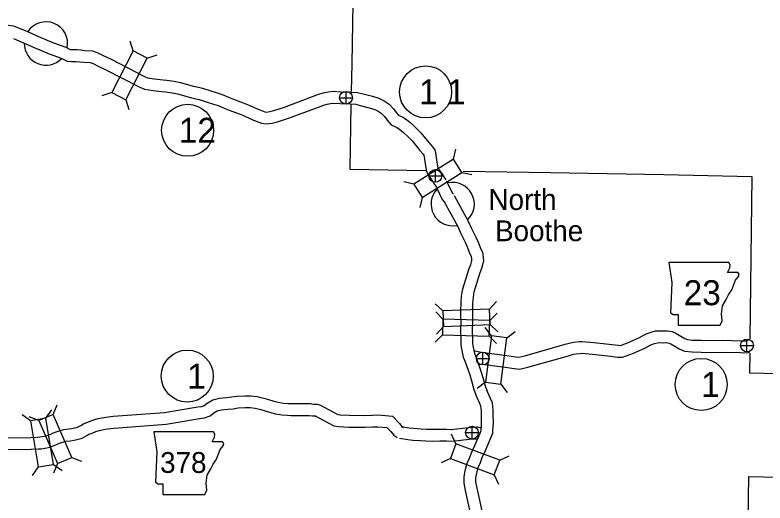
# Model space of a CAD drawing. Extents: x 1382482 to 1385815, y 1168351 to 1170484.
# Drawn here: x 1382910.5 to 1383100.9, y 1170230.6 to 1170354.4 of the extents above; entities that cross this region are included whole.
import ezdxf

# ---------------------------------------------------------------- set-up
doc = ezdxf.new("R2010")
doc.units = 0
for name, color, linetype in [('10', 7, 'Continuous'), ('15', 7, 'Continuous'), ('2', 7, 'Continuous'), ('20', 7, 'Continuous'), ('21', 7, 'Continuous'), ('24', 7, 'Continuous'), ('26', 7, 'Continuous'), ('8', 7, 'Continuous'), ('Default', 7, 'Continuous')]:
    doc.layers.add(name, color=color, linetype=linetype)

msp = doc.modelspace()

# ---------------------------------------------------------------- linework, layer by layer
at = {"layer": '10'}
for points in [[(1383026.89, 1170269.29), (1383028.93, 1170268.84), (1383035.31, 1170268.01), (1383037.57, 1170267.67), (1383038.43, 1170267.6), (1383039.96, 1170267.91), (1383050.2, 1170270.84), (1383051.56, 1170271.21), (1383052.44, 1170271.42), (1383053.74, 1170271.55), (1383054.43, 1170271.58), (1383057.44, 1170271.34), (1383060.56, 1170270.97), (1383062.04, 1170270.78), (1383063.69, 1170270.6), (1383064.19, 1170270.58), (1383066.39, 1170271.41), (1383069.08, 1170272.57), (1383070.72, 1170273.48), (1383071.99, 1170273.89), (1383073.1, 1170274.23), (1383074.17, 1170274.28), (1383075.25, 1170274.24), (1383076.14, 1170274.27), (1383077.31, 1170274.06), (1383078.29, 1170273.66), (1383079.57, 1170272.92), (1383080.52, 1170272.33), (1383081.23, 1170272.04), (1383082.54, 1170271.91), (1383084.76, 1170271.88), (1383090.15, 1170271.77)], [(1383028.1, 1170265.95), (1383028.41, 1170265.88), (1383034.9, 1170265.03), (1383037.21, 1170264.69), (1383038.6, 1170264.57), (1383040.68, 1170265), (1383051.01, 1170267.95), (1383052.3, 1170268.3), (1383052.93, 1170268.45), (1383053.97, 1170268.55), (1383054.39, 1170268.58), (1383057.14, 1170268.35), (1383060.19, 1170268), (1383061.68, 1170267.8), (1383063.48, 1170267.6), (1383064.69, 1170267.56), (1383067.51, 1170268.63), (1383070.4, 1170269.88), (1383071.91, 1170270.71), (1383072.89, 1170271.03), (1383073.62, 1170271.25), (1383074.19, 1170271.28), (1383075.23, 1170271.24), (1383075.92, 1170271.26), (1383076.48, 1170271.16), (1383076.96, 1170270.96), (1383078.03, 1170270.35), (1383079.14, 1170269.66), (1383080.49, 1170269.1), (1383082.38, 1170268.91), (1383084.71, 1170268.88), (1383090.08, 1170268.77)], [(1383096.92, 1170271.94), (1383096.46, 1170271.77), (1383096.01, 1170271.66), (1383095.43, 1170271.6), (1383094.9, 1170271.66), (1383090.15, 1170271.77)], [(1383096.98, 1170268.81), (1383096.54, 1170268.7), (1383095.42, 1170268.58), (1383094.69, 1170268.66), (1383090.08, 1170268.77)], [(1382904.92, 1170247.12), (1382914.45, 1170247.19), (1382916.19, 1170247.3), (1382916.76, 1170247.33), (1382917.97, 1170247.53), (1382918.45, 1170247.64), (1382919.28, 1170247.93), (1382920.67, 1170248.53), (1382921.67, 1170248.87), (1382922.88, 1170249.22), (1382924.13, 1170249.36), (1382924.98, 1170249.48), (1382925.55, 1170249.6), (1382926.03, 1170249.71), (1382926.33, 1170249.81), (1382927.19, 1170250.27), (1382927.84, 1170250.69), (1382928.9, 1170251.12), (1382930, 1170251.54), (1382930.7, 1170251.76), (1382931.58, 1170252), (1382932.48, 1170252.18), (1382933.5, 1170252.34), (1382935.35, 1170252.57), (1382948.45, 1170253.52), (1382952.38, 1170254.17), (1382956.89, 1170254.98), (1382957.93, 1170255.09), (1382958.48, 1170255.3), (1382959.24, 1170255.91), (1382960.7, 1170256.77), (1382962.4, 1170257.16), (1382964.19, 1170257.33), (1382965.48, 1170257.47), (1382966.8, 1170257.67), (1382968.82, 1170257.8), (1382970.32, 1170257.8), (1382971.97, 1170257.59), (1382973.64, 1170257.19), (1382974.82, 1170256.83), (1382976.17, 1170256.44), (1382977.24, 1170256.15), (1382978.6, 1170255.91), (1382979.83, 1170255.83), (1382980.6, 1170255.78), (1382982.29, 1170255.8), (1382983.65, 1170255.81), (1382985.37, 1170255.81), (1382986.26, 1170255.67), (1382987.2, 1170255.64), (1382988.06, 1170255.4), (1382988.93, 1170254.87), (1382992.4, 1170253.02), (1382992.99, 1170252.93), (1382995.28, 1170252.84), (1382999.21, 1170252.8), (1383001.27, 1170252.89), (1383002.68, 1170252.91), (1383006.3, 1170252.62), (1383008.09, 1170250.71), (1383008.68, 1170250.02), (1383009.15, 1170249.7)], [(1382905.04, 1170244.12), (1382914.56, 1170244.19), (1382916.37, 1170244.31), (1382917.09, 1170244.35), (1382918.54, 1170244.59), (1382919.28, 1170244.75), (1382920.37, 1170245.14), (1382921.75, 1170245.73), (1382922.58, 1170246.01), (1382923.47, 1170246.27), (1382924.51, 1170246.38), (1382925.5, 1170246.53), (1382926.18, 1170246.67), (1382926.86, 1170246.82), (1382927.52, 1170247.05), (1382928.72, 1170247.68), (1382929.24, 1170248.02), (1382930.01, 1170248.33), (1382930.98, 1170248.71), (1382931.54, 1170248.88), (1382932.27, 1170249.08), (1382933.01, 1170249.23), (1382933.92, 1170249.37), (1382935.64, 1170249.59), (1382948.8, 1170250.54), (1382952.89, 1170251.21), (1382957.31, 1170252.01), (1382958.61, 1170252.15), (1382959.99, 1170252.66), (1382960.95, 1170253.44), (1382961.82, 1170253.95), (1382962.88, 1170254.2), (1382964.49, 1170254.34), (1382965.87, 1170254.49), (1382967.13, 1170254.69), (1382968.92, 1170254.8), (1382970.13, 1170254.8), (1382971.43, 1170254.63), (1382972.86, 1170254.3), (1382973.96, 1170253.96), (1382975.36, 1170253.55), (1382976.59, 1170253.22), (1382978.23, 1170252.93), (1382979.64, 1170252.84), (1382980.52, 1170252.78), (1382982.32, 1170252.8), (1382983.67, 1170252.81), (1382985.13, 1170252.81), (1382985.98, 1170252.67), (1382986.75, 1170252.65), (1382986.85, 1170252.62), (1382987.45, 1170252.26), (1382991.45, 1170250.12), (1382992.72, 1170249.94), (1382995.2, 1170249.84), (1382999.27, 1170249.79), (1383001.36, 1170249.89), (1383002.58, 1170249.9), (1383004.9, 1170249.72), (1383005.86, 1170248.7), (1383006.67, 1170247.76), (1383007.46, 1170247.22)], [(1383008.52, 1170249.95), (1383010.57, 1170249.64), (1383011.69, 1170249.53), (1383013.61, 1170249.43), (1383014.98, 1170249.31), (1383016.41, 1170249.28), (1383018.34, 1170249.33), (1383020.1, 1170249.31), (1383021.47, 1170249.26)], [(1383021.25, 1170249.25), (1383025.51, 1170249.73), (1383026.76, 1170249.84), (1383027.86, 1170249.89), (1383028.82, 1170249.68), (1383028.84, 1170249.67)], [(1383008.08, 1170246.98), (1383010.2, 1170246.66), (1383011.46, 1170246.54), (1383013.41, 1170246.43), (1383014.82, 1170246.31), (1383016.42, 1170246.28), (1383018.37, 1170246.33), (1383020.03, 1170246.31), (1383021.37, 1170246.26)], [(1383021.59, 1170246.27), (1383025.81, 1170246.75), (1383026.96, 1170246.84), (1383027.61, 1170246.87), (1383027.94, 1170246.8)]]:
    msp.add_lwpolyline(points, dxfattribs=at)
at = {"layer": '15'}
for points in [[(1382902.49, 1170352.31), (1382903.65, 1170352.27), (1382904.86, 1170352.14), (1382905.89, 1170351.99), (1382907.07, 1170351.92), (1382908.14, 1170351.92), (1382910.04, 1170351.7), (1382911.34, 1170351.17), (1382913.65, 1170350.24)], [(1382913.64, 1170350.2), (1382916.46, 1170348.96), (1382920.23, 1170347.4), (1382923.33, 1170346.27), (1382924.49, 1170345.69), (1382924.95, 1170345.66), (1382926.14, 1170345.63), (1382927.21, 1170345.55), (1382928.16, 1170345.43), (1382930.12, 1170345.35), (1382931.48, 1170344.83), (1382932.88, 1170344.14), (1382934.87, 1170343.2), (1382943.38, 1170338.81), (1382944.12, 1170338.51), (1382945.91, 1170338.22), (1382948.09, 1170337.97), (1382949.04, 1170337.87), (1382950.86, 1170337.67), (1382952.48, 1170337.3), (1382955.73, 1170336.4), (1382957.05, 1170336.1), (1382958.04, 1170335.88), (1382959.66, 1170335.34), (1382961.78, 1170334.67), (1382963.03, 1170334.27), (1382964.67, 1170333.6), (1382965.94, 1170333.1), (1382969.49, 1170331.73), (1382971.78, 1170330.69), (1382973.9, 1170329.85), (1382974.22, 1170329.79), (1382975.17, 1170329.9), (1382976.18, 1170330.21), (1382978.89, 1170331.07), (1382987.13, 1170334.13), (1382987.88, 1170334.42), (1382989.03, 1170334.72), (1382990.08, 1170334.93), (1382991.14, 1170335.07), (1382991.32, 1170335.05)], [(1382910.05, 1170348.5), (1382915.28, 1170346.21), (1382919.14, 1170344.6), (1382922.14, 1170343.51), (1382923.68, 1170342.74), (1382924.82, 1170342.66), (1382925.99, 1170342.63), (1382926.9, 1170342.57), (1382927.9, 1170342.43), (1382929.52, 1170342.37), (1382930.28, 1170342.08), (1382931.57, 1170341.44), (1382933.54, 1170340.51), (1382942.12, 1170336.08), (1382943.3, 1170335.6), (1382945.5, 1170335.25), (1382947.76, 1170334.99), (1382948.71, 1170334.89), (1382950.37, 1170334.7), (1382951.75, 1170334.39), (1382954.99, 1170333.49), (1382956.39, 1170333.18), (1382957.23, 1170332.99), (1382958.73, 1170332.48), (1382960.88, 1170331.81), (1382962.01, 1170331.45), (1382963.55, 1170330.82), (1382964.84, 1170330.31), (1382968.33, 1170328.96), (1382970.61, 1170327.93), (1382973.08, 1170326.94), (1382974.14, 1170326.77), (1382975.78, 1170326.95), (1382977.08, 1170327.35), (1382979.87, 1170328.23), (1382988.19, 1170331.32), (1382988.81, 1170331.56), (1382989.71, 1170331.8), (1382990.56, 1170331.97), (1382991.19, 1170332.05)], [(1382991.24, 1170335.06), (1382993.16, 1170334.96)], [(1382993.16, 1170334.96), (1382995.81, 1170334.83), (1382997.41, 1170334.74), (1382998.86, 1170334.38), (1383001.2, 1170333.79), (1383002.88, 1170333.28), (1383004.2, 1170332.64), (1383005.45, 1170331.77), (1383006.53, 1170330.6), (1383007.29, 1170329.67), (1383007.81, 1170329.04), (1383008.22, 1170328.86), (1383008.92, 1170328.51), (1383009.86, 1170327.92), (1383011.12, 1170326.86), (1383012.53, 1170325.51), (1383013.52, 1170324.48), (1383014.67, 1170323.12), (1383015.59, 1170321.99), (1383016.47, 1170320.95), (1383017.06, 1170320.17), (1383017.22, 1170319.47), (1383017.43, 1170318.25), (1383017.58, 1170317.1), (1383017.85, 1170315.65), (1383017.99, 1170315.36), (1383018.2, 1170315), (1383018.77, 1170314.29), (1383019.5, 1170313.12), (1383019.9, 1170312.57)], [(1382991.09, 1170332.06), (1382993.02, 1170331.97)], [(1382993.02, 1170331.97), (1382995.65, 1170331.84), (1382996.97, 1170331.76), (1382998.14, 1170331.47), (1383000.39, 1170330.9), (1383001.79, 1170330.47), (1383002.68, 1170330.05), (1383003.46, 1170329.5), (1383004.26, 1170328.63), (1383004.97, 1170327.76), (1383005.96, 1170326.57), (1383006.95, 1170326.14), (1383007.44, 1170325.9), (1383008.09, 1170325.49), (1383009.12, 1170324.62), (1383010.41, 1170323.39), (1383011.29, 1170322.47), (1383012.36, 1170321.21), (1383013.28, 1170320.07), (1383014.13, 1170319.08), (1383014.27, 1170318.88), (1383014.28, 1170318.87), (1383014.46, 1170317.8), (1383014.61, 1170316.64), (1383014.97, 1170314.71), (1383015.34, 1170313.94), (1383015.73, 1170313.29), (1383016.32, 1170312.55), (1383017.02, 1170311.44), (1383017.47, 1170310.82)], [(1383020.06, 1170312.3), (1383020.47, 1170311.35), (1383020.93, 1170310.36), (1383021.47, 1170309.27), (1383021.78, 1170308.92)], [(1383017.31, 1170311.09), (1383017.74, 1170310.12), (1383018.22, 1170309.07), (1383018.95, 1170307.59), (1383019.52, 1170306.94)], [(1383021.97, 1170308.65), (1383025.57, 1170302.06), (1383026.3, 1170300.44), (1383027.59, 1170297.89), (1383028.08, 1170296.74), (1383028.75, 1170295), (1383029.13, 1170294.22), (1383029.23, 1170293.73), (1383029.38, 1170292.87), (1383029.46, 1170292.05), (1383029.29, 1170291.31), (1383028.96, 1170290.08), (1383028.53, 1170288.97), (1383026.98, 1170284.07), (1383026.86, 1170283.54), (1383026.76, 1170282.75), (1383026.64, 1170281.35), (1383026.6, 1170279.13), (1383026.59, 1170277.98), (1383026.64, 1170276.65), (1383026.58, 1170274.24), (1383026.63, 1170272.29), (1383026.67, 1170271.02), (1383026.71, 1170270.51), (1383027.1, 1170268.48), (1383027.54, 1170267.53), (1383028.79, 1170264.04), (1383029.35, 1170262.13), (1383029.85, 1170260.26), (1383030.43, 1170258.71), (1383031.11, 1170257.16), (1383031.62, 1170256.04), (1383031.81, 1170254), (1383031.81, 1170252.93), (1383031.85, 1170251.04), (1383031.8, 1170249.82), (1383031.75, 1170248.9), (1383031.69, 1170248.17), (1383031.23, 1170247.02), (1383029.86, 1170243.83), (1383029.04, 1170242.05), (1383028.56, 1170240.76), (1383028.01, 1170239.49), (1383027.78, 1170238.89), (1383027.53, 1170237.75), (1383027.42, 1170236.91), (1383027.43, 1170235.91), (1383027.74, 1170234.31), (1383028.37, 1170231.29), (1383029, 1170228.53)], [(1383019.34, 1170307.21), (1383022.88, 1170300.72), (1383023.59, 1170299.15), (1383024.87, 1170296.62), (1383025.3, 1170295.61), (1383025.99, 1170293.81), (1383026.27, 1170293.23), (1383026.29, 1170293.16), (1383026.4, 1170292.48), (1383026.42, 1170292.24), (1383026.38, 1170292.02), (1383026.1, 1170291.01), (1383025.7, 1170289.96), (1383024.07, 1170284.84), (1383023.91, 1170284.06), (1383023.78, 1170283.08), (1383023.64, 1170281.51), (1383023.6, 1170279.17), (1383023.59, 1170277.94), (1383023.64, 1170276.63), (1383023.58, 1170274.24), (1383023.64, 1170272.21), (1383023.68, 1170270.88), (1383023.73, 1170270.13), (1383024.22, 1170267.56), (1383024.76, 1170266.39), (1383025.94, 1170263.11), (1383026.46, 1170261.32), (1383026.99, 1170259.34), (1383027.65, 1170257.58), (1383028.37, 1170255.93), (1383028.68, 1170255.25), (1383028.81, 1170253.85), (1383028.81, 1170252.9), (1383028.84, 1170251.07), (1383028.81, 1170249.95), (1383028.76, 1170249.11), (1383028.74, 1170248.86), (1383028.46, 1170248.17), (1383027.12, 1170245.05), (1383026.26, 1170243.21), (1383025.77, 1170241.88), (1383025.23, 1170240.61), (1383024.9, 1170239.75), (1383024.57, 1170238.27), (1383024.42, 1170237.09), (1383024.43, 1170235.61), (1383024.8, 1170233.72), (1383025.44, 1170230.65), (1383026.05, 1170227.97)]]:
    msp.add_lwpolyline(points, dxfattribs=at)
at = {"layer": '2'}
for points in [[(1382996.81, 1170384.74), (1382996.41, 1170367.85), (1382995.95, 1170342), (1382995.82, 1170335.03)], [(1382995.76, 1170331.67), (1382995.45, 1170315.28), (1383014.79, 1170314.92)], [(1383024.3, 1170314.76), (1383046.47, 1170314.47), (1383075.2, 1170313.9), (1383097.6, 1170313.46), (1383097.09, 1170272.2)], [(1383097.05, 1170268.6), (1383096.99, 1170263.64), (1383122.86, 1170263.02), (1383150.79, 1170262.42), (1383177.31, 1170261.44), (1383177.31, 1170261.79), (1383203.68, 1170261.89), (1383208.05, 1170261.93)]]:
    msp.add_lwpolyline(points, dxfattribs=at)
at = {"layer": '20'}
for p, q in [((1382940.49, 1170345.29), (1382939.69, 1170347.81)), ((1382944.01, 1170343.48), (1382946.53, 1170344.28)), ((1382935.05, 1170334.73), (1382932.54, 1170333.93)), ((1382938.57, 1170332.92), (1382939.37, 1170330.41)), ((1383021.78, 1170317.83), (1383022.36, 1170320.4)), ((1383023.9, 1170314.48), (1383026.47, 1170313.9)), ((1383011.74, 1170311.48), (1383009.16, 1170312.06)), ((1383013.86, 1170308.13), (1383013.28, 1170305.56)), ((1383030.97, 1170279.79), (1383032.76, 1170281.72)), ((1383019.09, 1170279.33), (1383017.16, 1170281.12)), ((1383019.12, 1170277.19), (1383017.3, 1170279.1)), ((1383031, 1170276.9), (1383032.91, 1170278.72)), ((1383019.32, 1170277.18), (1383019.12, 1170277.19)), ((1383019.25, 1170275.37), (1383017.45, 1170273.43)), ((1383031.45, 1170272.99), (1383029.84, 1170275.08)), ((1383031.12, 1170275.83), (1383033.05, 1170274.03)), ((1383035.38, 1170272.48), (1383037.47, 1170274.08)), ((1383019.03, 1170273.23), (1383017.11, 1170271.41)), ((1383030.9, 1170272.94), (1383032.72, 1170271.03)), ((1383029.91, 1170261.21), (1383027.81, 1170259.6)), ((1383033.83, 1170260.7), (1383035.44, 1170258.6)), ((1382920.17, 1170253.05), (1382921.15, 1170255.5)), ((1382918.29, 1170252.09), (1382919.83, 1170254.24)), ((1382914.39, 1170251.44), (1382912.24, 1170252.97)), ((1382916.54, 1170251.49), (1382914.08, 1170252.47)), ((1383022.42, 1170245.6), (1383021.32, 1170248)), ((1382924.86, 1170242.13), (1382927.31, 1170241.15)), ((1383021.04, 1170241.89), (1383018.64, 1170240.79)), ((1383033.55, 1170241.46), (1383035.95, 1170242.56)), ((1382916.35, 1170239.72), (1382914.82, 1170237.57)), ((1382921.22, 1170240.57), (1382920.24, 1170238.12)), ((1382920.26, 1170240.37), (1382922.41, 1170238.84)), ((1383032.17, 1170237.75), (1383033.27, 1170235.35))]:
    msp.add_line(p, q, dxfattribs=at)
for points in [[(1382940.49, 1170345.29), (1382935.05, 1170334.73), (1382938.57, 1170332.92), (1382944.01, 1170343.48)], [(1383013.86, 1170308.13), (1383023.9, 1170314.48), (1383021.78, 1170317.83), (1383011.74, 1170311.48)], [(1383019.25, 1170275.37), (1383031.12, 1170275.83), (1383030.97, 1170279.79), (1383019.09, 1170279.33)], [(1383019.03, 1170273.23), (1383030.9, 1170272.94), (1383031, 1170276.9), (1383019.12, 1170277.19)], [(1383031.45, 1170272.99), (1383029.91, 1170261.21), (1383033.83, 1170260.7), (1383035.38, 1170272.48)], [(1382924.86, 1170242.13), (1382920.17, 1170253.05), (1382916.54, 1170251.49), (1382921.22, 1170240.57)], [(1382920.26, 1170240.37), (1382918.29, 1170252.09), (1382914.39, 1170251.44), (1382916.35, 1170239.72)], [(1383033.55, 1170241.46), (1383022.42, 1170245.6), (1383021.04, 1170241.89), (1383032.17, 1170237.75)]]:
    msp.add_lwpolyline(points, close=True, dxfattribs=at)
at = {"layer": '21'}
for points in [[(1383076.5, 1170291.58), (1383077.26, 1170286.51), (1383076.92, 1170278.81), (1383077.6, 1170278.39), (1383078.87, 1170278.39), (1383078.87, 1170275.68), (1383089.53, 1170275.68), (1383090.04, 1170276.78), (1383089.87, 1170278.55), (1383090.12, 1170280.58), (1383091.05, 1170282.19), (1383091.64, 1170283.38), (1383092.49, 1170284.65), (1383093, 1170286), (1383093.42, 1170287.1), (1383094.18, 1170288.03), (1383094.35, 1170288.62), (1383094.01, 1170289.04), (1383091.39, 1170289.04), (1383091.98, 1170290.23), (1383092.07, 1170290.99), (1383091.71, 1170291.57)], [(1382945.67, 1170248.64), (1382946.43, 1170243.57), (1382946.09, 1170235.87), (1382946.77, 1170235.45), (1382948.03, 1170235.45), (1382948.03, 1170232.74), (1382958.69, 1170232.74), (1382959.2, 1170233.84), (1382959.03, 1170235.62), (1382959.29, 1170237.65), (1382960.22, 1170239.25), (1382960.81, 1170240.44), (1382961.65, 1170241.71), (1382962.16, 1170243.06), (1382962.58, 1170244.16), (1382963.35, 1170245.09), (1382963.51, 1170245.68), (1382963.18, 1170246.11), (1382960.55, 1170246.11), (1382961.15, 1170247.29), (1382961.23, 1170248.05), (1382960.88, 1170248.64)]]:
    msp.add_lwpolyline(points, close=True, dxfattribs=at)
at = {"layer": '24'}
for centre, start, end in [((1382918.32, 1170347.19), 348.435, 146.7325), ((1382918.32, 1170347.19), 179.2843, 316.5397), ((1383021.61, 1170306.43), 136.0382, 280.9733), ((1383021.61, 1170306.43), 312.9781, 102.345)]:
    msp.add_arc(centre, 5.5, start, end, dxfattribs=at)
at = {"layer": '26'}
for p, q in [((1382994.51, 1170331.8), (1382994.51, 1170335.05)), ((1382992.88, 1170333.42), (1382996.13, 1170333.42)), ((1383017.2, 1170311.96), (1383017.2, 1170315.21)), ((1383015.58, 1170313.58), (1383018.83, 1170313.58)), ((1383096.33, 1170268.92), (1383096.33, 1170272.17)), ((1383094.71, 1170270.55), (1383097.96, 1170270.55)), ((1383029.23, 1170265.6), (1383029.23, 1170268.85)), ((1383027.61, 1170267.23), (1383030.86, 1170267.23)), ((1383026.51, 1170246.79), (1383026.51, 1170250.04)), ((1383024.89, 1170248.42), (1383028.14, 1170248.42))]:
    msp.add_line(p, q, dxfattribs=at)
for centre in [(1382994.51, 1170333.42), (1383017.2, 1170313.58), (1383096.33, 1170270.55), (1383029.23, 1170267.23), (1383026.51, 1170248.42)]:
    msp.add_circle(centre, 1.62, dxfattribs=at)
at = {"layer": '8'}
msp.add_lwpolyline([(1383096.49, 1170215.03), (1383096.82, 1170237.25), (1383122.6, 1170236.68), (1383150.22, 1170235.97), (1383176.91, 1170235.2), (1383176.95, 1170235.7), (1383203.59, 1170235.9), (1383203.66, 1170261.85)], dxfattribs=at)
at = {"layer": 'Default'}
for centre in [(1383014.72, 1170334.91), (1382954.29, 1170325.16), (1382954.19, 1170262.78), (1383084.7, 1170260.65)]:
    msp.add_circle(centre, 6.6, dxfattribs=at)

# ---------------------------------------------------------------- texts
at = {"layer": '21'}
for s, height, p in [('23', 6.336, (1383080.26, 1170280.77)), ('378', 5.28, (1382947.3, 1170238.2))]:
    msp.add_text(s, height=height, dxfattribs=at).set_placement(p)
at = {"layer": '24'}
for s, p in [('North', (1383030.7, 1170304.94)), ('Boothe', (1383032.36, 1170297.01))]:
    msp.add_text(s, height=5.28, dxfattribs=at).set_placement(p)
at = {"layer": 'Default'}
for s, height, p in [('1 1', 6.336, (1383013.07, 1170331.75)), ('12', 6.336, (1382952.05, 1170321.99)), ('1', 6.34, (1382954.19, 1170259.61)), ('1', 6.34, (1383084.7, 1170257.48))]:
    msp.add_text(s, height=height, dxfattribs=at).set_placement(p)

doc.saveas('drawing.dxf')
